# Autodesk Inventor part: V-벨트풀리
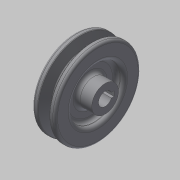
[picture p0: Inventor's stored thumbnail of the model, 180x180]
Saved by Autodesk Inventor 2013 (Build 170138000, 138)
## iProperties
Created: 2015-02
Part Number: V-벨트풀리
Material: 일반
Document SubType Name: Modeling
Designer: Administrator
Density: 1 g/cm^3
Author: Administrator
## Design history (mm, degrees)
sketch "스케치1"
  geometry: L1 (0, 0)-(25, 0); L2 (0, 5.5)-(0, 11); L3 (0, 11)-(6.5, 11); L4 (6.5, 11)-(6.5, 21.5); L5 (6.5, 21.5)-(0, 21.5); L6 (0, 21.5)-(0, 35.2); L7 (0, 35.2)-(4.675, 35.2); L8 (4.675, 35.2)-(7.426, 26.2); L9 (7.426, 26.2)-(11.574, 26.2); L10 (11.574, 26.2)-(14.325, 35.2); L11 (14.325, 35.2)-(19, 35.2); L12 (19, 35.2)-(19, 21.5); L13 (19, 21.5)-(12.5, 21.5); L14 (12.5, 21.5)-(12.5, 11); L15 (12.5, 11)-(25, 11); L16 (25, 11)-(25, 5.5); L17 (25, 5.5)-(0, 5.5); L18 (5.5, 32.5)-(13.5, 32.5); 2 further points
  constraints: 36 end point, 6 equal length, 4 horizontal, 3 parallel, 2 midpoint, 2 point on line, 2 vertical alignment, 1 collinear, 1 perpendicular
  dimensions: "d0" = 25 distance of L1.start L1.end; "d2" = 34 deg angle of L10 L8; "d3" = 19 distance between parallel lines of L12 L6; "d4" = 25 distance between parallel lines of L16 L6; "d5" = 11 diameter of L17 L1; "d6" = 22 diameter of L15 L1; "d7" = 43 diameter of L5 L1; "d8" = 6 distance between parallel lines of L14 L4; "d9" = 8 distance of L18.end L18.start; "d10" = 65 diameter of L18 L1; "d11" = 6.3 distance between parallel lines of L9 L18; "d12" = 2.7 distance between parallel lines of L18 L11; "d13" = 6.5 distance from line of L1.start L4
revolve "회전1" sketch "스케치1" stored, may be unused: angle "d14" = 90 deg
fillet "모깎기1" dims "d15" = 1, "d16" = 0.5, "d17" = 2
fillet "모깎기2" dims "d18" = 3
sketch "스케치2"
  geometry: L1 (-2, 7.3)-(2, 7.3); L2 (2, 7.3)-(2, 5.123); L3 (-2, 5.123)-(-2, 7.3); L4 (-2, 5.123)-(2, 5.123); 2 further points
  constraints: 8 end point, 2 perpendicular, 1 horizontal, 1 midpoint, 1 parallel, 1 vertical alignment, 2 other
  dimensions: "d19" = 12.8 dimension on L1; "d20" = 4 distance between parallel lines of L2 L3
extrude "돌출1" cut sketch "스케치2" distance "d21" = 33.5; taper "d22" = 0 deg
node "솔리드1"
